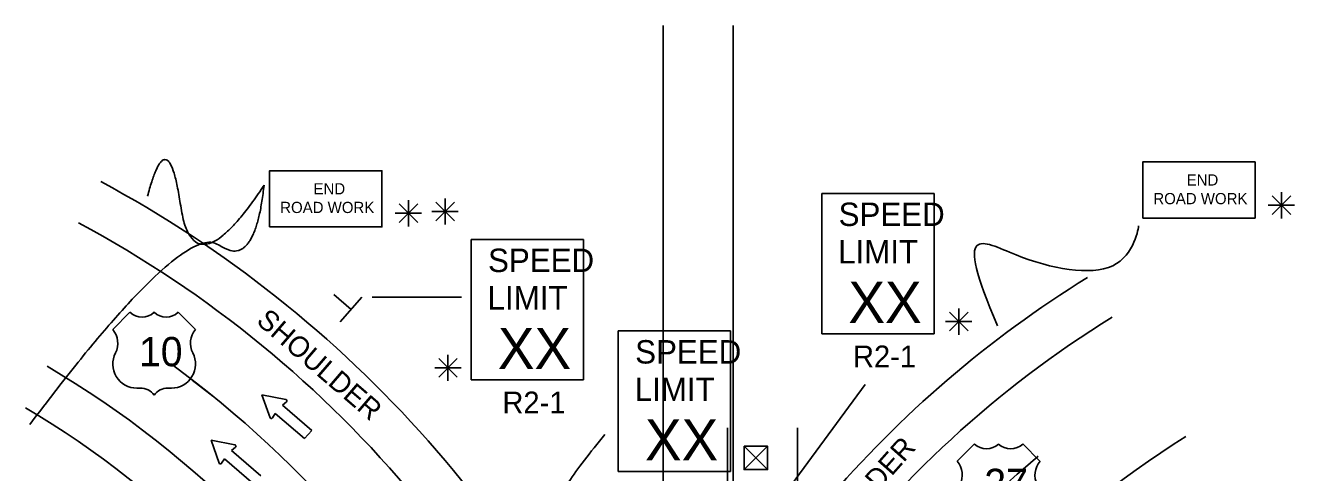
# Model space of a CAD drawing. Extents: x 16335 to 18464, y 5417 to 6974.
# Drawn here: x 16726.3 to 17160.2, y 6821.2 to 6974.1 of the extents above; entities that cross this region are included whole.
import ezdxf

# ---------------------------------------------------------------- set-up
doc = ezdxf.new("R2010")
doc.units = 0
for name, color, linetype in [('ALI_LEGAL_EX', 7, 'Continuous'), ('MT_SCRATCH_LEVEL_E', 7, 'Continuous'), ('PAVT_EDGE_EX', 7, 'Continuous'), ('TRAFFIC_SIGNS_PR', 7, 'Continuous'), ('TYPICAL_EX', 7, 'Continuous'), ('TYPICAL_TEXT_DIMEN_PR', 7, 'Continuous')]:
    doc.layers.add(name, color=color, linetype=linetype)

msp = doc.modelspace()

# ---------------------------------------------------------------- linework, layer by layer
at = {"layer": 'ALI_LEGAL_EX'}
for p, q in [((16944.3, 6974.12), (16944.3, 6155.98)), ((16968.3, 6974.12), (16968.3, 6155.98)), ((16966.29, 6836.53), (16966.29, 5997.6)), ((16990.29, 6836.53), (16990.29, 5997.6))]:
    msp.add_line(p, q, dxfattribs=at)
for points in [[(16968.3, 6949.12), (16968.3, 6974.12)], [(16790.41, 6847.41), (16783.31, 6852.89)]]:
    msp.add_lwpolyline(points, dxfattribs=at)
for centre, radius, start, end in [((16561.13, 6564.7), 364, 0, 53.7921), ((17289.13, 6564.7), 340, 129.5666, 180)]:
    msp.add_arc(centre, radius, start, end, dxfattribs=at)
at = {"layer": 'MT_SCRATCH_LEVEL_E'}
for p, q in [((16815.35, 6846.27), (16807.16, 6847.85)), ((16807.16, 6847.85), (16809.97, 6840.01)), ((16814.16, 6844.32), (16815.56, 6845.47)), ((16824.21, 6835.68), (16814.16, 6844.32)), ((16810.8, 6839.93), (16811.72, 6841.49)), ((16811.72, 6841.49), (16821.77, 6832.84)), ((16821.77, 6832.84), (16824.21, 6835.68)), ((16797.97, 6830.75), (16789.78, 6832.33)), ((16789.78, 6832.33), (16792.59, 6824.49)), ((16796.78, 6828.8), (16798.18, 6829.94)), ((16806.83, 6820.15), (16796.78, 6828.8)), ((16793.42, 6824.41), (16794.34, 6825.96)), ((16794.34, 6825.96), (16804.39, 6817.32))]:
    msp.add_line(p, q, dxfattribs=at)
for centre, start, end in [((16815.26, 6845.82), 309.3361, 79.073), ((16810.4, 6840.18), 199.7248, 329.2637), ((16797.88, 6830.29), 309.3361, 79.073), ((16793.02, 6824.65), 199.7248, 329.2637)]:
    msp.add_arc(centre, 0.463, start, end, dxfattribs=at)
at = {"layer": 'PAVT_EDGE_EX'}
for centre, radius, start, end in [((16561.13, 6564.7), 404, 21.0961, 61.7914), ((16561.13, 6564.7), 388, 17.512, 61.7914), ((17289.13, 6564.7), 380, 121.7103, 157.5011), ((17289.13, 6564.7), 364, 121.7103, 165.0045), ((16561.13, 6564.7), 340, 0, 59.4823), ((16561.13, 6564.7), 324, 0, 59.3448), ((17289.13, 6564.7), 316, 121.7103, 180)]:
    msp.add_arc(centre, radius, start, end, dxfattribs=at)
at = {"layer": 'TRAFFIC_SIGNS_PR'}
for p, q in [((16998.53, 6916.68), (17036.93, 6916.68)), ((16998.53, 6868.68), (16998.53, 6916.68)), ((17036.93, 6868.68), (17036.93, 6916.68)), ((16878.7, 6900.93), (16917.1, 6900.93)), ((16878.7, 6852.93), (16878.7, 6900.93)), ((16917.1, 6852.93), (16917.1, 6900.93)), ((16928.99, 6869.65), (16967.39, 6869.65)), ((16928.99, 6821.65), (16928.99, 6869.65)), ((16967.39, 6821.65), (16967.39, 6869.65)), ((16998.53, 6868.68), (17036.93, 6868.68)), ((16878.7, 6852.93), (16917.1, 6852.93)), ((16928.99, 6821.65), (16967.39, 6821.65))]:
    msp.add_line(p, q, dxfattribs=at)
for points in [[(16809.82, 6905.22), (16848.22, 6905.22), (16848.22, 6924.42), (16809.82, 6924.42)], [(17108.26, 6908.24), (17146.66, 6908.24), (17146.66, 6927.44), (17108.26, 6927.44)]]:
    msp.add_lwpolyline(points, close=True, dxfattribs=at)
at = {"layer": 'TYPICAL_EX'}
for p, q in [((16756.18, 6870.17), (16762.08, 6876.06)), ((16784.48, 6870.17), (16778.59, 6876.06)), ((16764.43, 6850.11), (16765.61, 6850.11)), ((16776.24, 6850.11), (16775.06, 6850.11)), ((17044.83, 6825.12), (17050.72, 6831.02)), ((17073.13, 6825.12), (17067.23, 6831.02))]:
    msp.add_line(p, q, dxfattribs=at)
for centre, radius, start, end in [((16766.21, 6880.36), 5.96, 226.1404, 313.8596), ((16774.46, 6880.36), 5.96, 226.1404, 313.8596), ((16750.6, 6865.45), 7.31, 333.0977, 40.1936), ((16790.07, 6865.45), 7.31, 139.8064, 206.9023), ((16764.44, 6858.35), 8.24, 152.6698, 269.9013), ((16776.22, 6858.35), 8.24, 270.0987, 27.3302), ((16765.62, 6844.2), 5.91, 37.1038, 90.1385), ((16775.04, 6844.2), 5.91, 89.8615, 142.8962), ((17054.85, 6835.31), 5.96, 226.1404, 313.8596), ((17063.11, 6835.31), 5.96, 226.1404, 313.8596), ((17039.24, 6820.4), 7.31, 333.0977, 40.1936), ((17078.72, 6820.4), 7.31, 139.8064, 206.9023)]:
    msp.add_arc(centre, radius, start, end, dxfattribs=at)
at = {"layer": 'TYPICAL_TEXT_DIMEN_PR'}
for p, q in [((17158.87, 6915.81), (17152.49, 6909.43)), ((17152.5, 6915.81), (17158.87, 6909.43)), ((17155.68, 6912.62), (17155.68, 6917.07)), ((16854.06, 6913.1), (16860.43, 6906.72)), ((16860.43, 6913.1), (16854.06, 6906.72)), ((16857.24, 6909.91), (16857.24, 6914.36)), ((16866.61, 6913.72), (16872.99, 6907.35)), ((16872.99, 6913.72), (16866.61, 6907.35)), ((16869.8, 6910.53), (16869.8, 6914.99)), ((17155.68, 6912.62), (17151.15, 6912.62)), ((17155.68, 6912.62), (17158.87, 6912.62)), ((17155.68, 6912.62), (17160.16, 6912.62)), ((17155.68, 6912.62), (17155.68, 6908.12)), ((16857.24, 6909.91), (16852.71, 6909.91)), ((16857.24, 6909.91), (16860.43, 6909.91)), ((16857.24, 6909.91), (16861.72, 6909.91)), ((16857.24, 6909.91), (16857.24, 6905.41)), ((16869.8, 6910.53), (16865.27, 6910.53)), ((16869.8, 6910.53), (16872.99, 6910.53)), ((16869.8, 6910.53), (16874.28, 6910.53)), ((16869.8, 6910.53), (16869.8, 6906.03)), ((16837.65, 6876.99), (16831.75, 6882.07)), ((16841.32, 6881.26), (16833.98, 6872.73)), ((16844.86, 6881.26), (16875.44, 6881.26)), ((17045.35, 6872.86), (17045.35, 6877.31)), ((17045.35, 6872.86), (17040.82, 6872.86)), ((17042.16, 6876.04), (17048.54, 6869.67)), ((17048.54, 6876.04), (17042.16, 6869.67)), ((17045.35, 6872.86), (17048.54, 6872.86)), ((17045.35, 6872.86), (17049.83, 6872.86)), ((17045.35, 6872.86), (17045.35, 6868.36)), ((16867.6, 6860.28), (16873.97, 6853.9)), ((16873.97, 6860.28), (16867.6, 6853.9)), ((16870.78, 6857.09), (16870.78, 6861.55)), ((16870.78, 6857.09), (16866.25, 6857.09)), ((16870.78, 6857.09), (16873.97, 6857.09)), ((16870.78, 6857.09), (16875.26, 6857.09)), ((16870.78, 6857.09), (16870.78, 6852.59)), ((16957.13, 6775.18), (17013.42, 6851.3)), ((16972, 6822.26), (16980, 6830.26)), ((16972, 6830.25), (16980, 6822.26))]:
    msp.add_line(p, q, dxfattribs=at)
msp.add_lwpolyline([(16972, 6830.25), (16972, 6822.26), (16980, 6822.26), (16980, 6830.26)], close=True, dxfattribs=at)
for points, degree in [([(16768.07, 6915.7), (16775.05, 6942.33), (16783.68, 6882.84), (16807.9, 6919.45)], 2), ([(16727.82, 6837.66), (16780.55, 6907.8), (16804.75, 6890.22), (16807.9, 6919.45)], 2), ([(17058.66, 6871.45), (17043.1, 6907.35), (17063.13, 6893.41), (17104.12, 6885.91), (17106.85, 6905.18), (17106.83, 6905.54)], 3), ([(16909.99, 6783.05), (16925.05, 6790.93), (16915.89, 6798.15), (16900.83, 6806.02), (16924.4, 6834.24)], 2)]:
    msp.add_open_spline(points, degree=degree, dxfattribs=at)

# ---------------------------------------------------------------- texts
at = {"layer": 'TRAFFIC_SIGNS_PR'}
for s, height, p in [('END', 3.831, (16824.82, 6916.35)), ('END', 3.831, (17123.26, 6919.37)), ('ROAD WORK', 3.831, (17111.87, 6912.99)), ('ROAD WORK', 3.831, (16813.43, 6909.97)), ('SPEED', 8, (17004.3, 6905.54)), ('SPEED', 8, (16884.47, 6889.8)), ('LIMIT', 8, (17004.14, 6892.74)), ('LIMIT', 8, (16884.31, 6876.99)), ('XX', 14.031, (17007.64, 6872.43)), ('XX', 14.031, (16887.82, 6856.69)), ('SPEED', 8, (16934.76, 6858.52)), ('R2-1', 7.44, (17009.21, 6857.24)), ('LIMIT', 8, (16934.6, 6845.72)), ('R2-1', 7.44, (16889.38, 6841.49)), ('XX', 14.031, (16938.11, 6825.41))]:
    msp.add_text(s, height=height, dxfattribs=at).set_placement(p)
at = {"layer": 'TYPICAL_EX'}
for s, p in [('10', (16765.18, 6857.6)), ('27', (17054.09, 6812.55))]:
    msp.add_text(s, height=10, dxfattribs=at).set_placement(p)
at = {"layer": 'TYPICAL_TEXT_DIMEN_PR'}
for rotation, p in [(319.2839, (16804.92, 6872.51)), (48.378, (16996.49, 6790.64))]:
    msp.add_text('SHOULDER', height=7, rotation=rotation, dxfattribs=at).set_placement(p)

doc.saveas('drawing.dxf')
